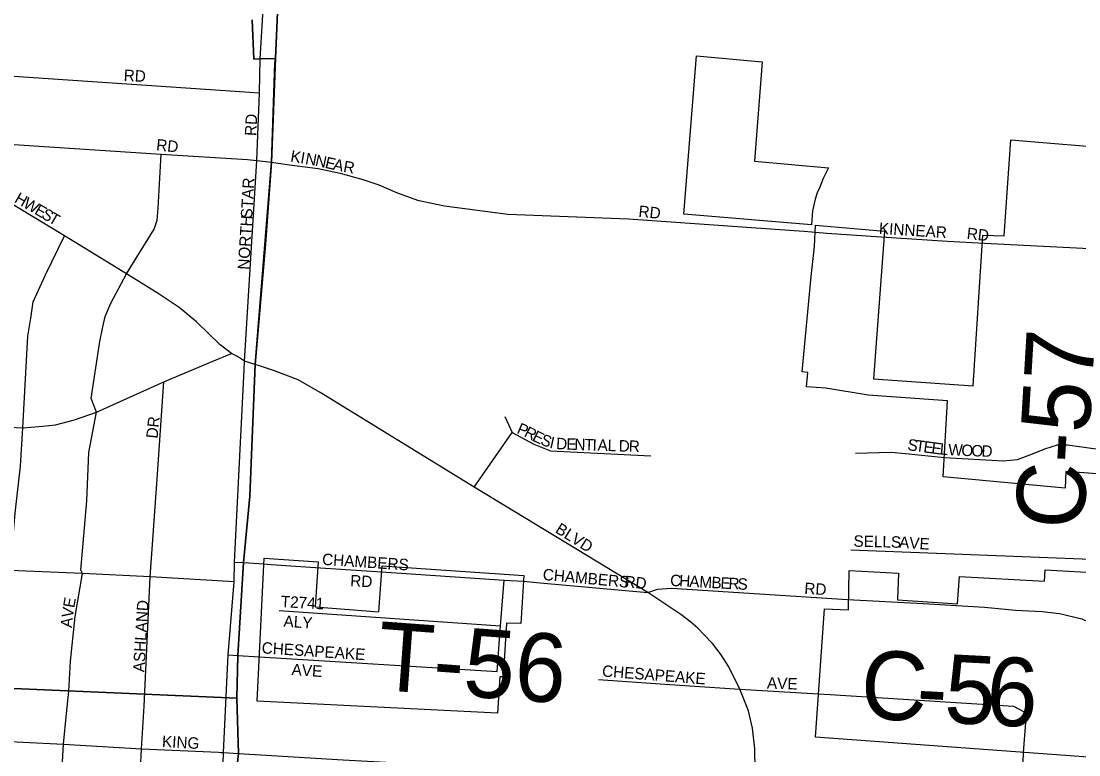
# Model space of a CAD drawing. Extents: x 0 to 34, y -6.2 to 22.
# Drawn here: x 3.949 to 4.825, y 20.105 to 20.712 of the extents above; entities that cross this region are included whole.
import ezdxf

# ---------------------------------------------------------------- set-up
doc = ezdxf.new("R2010")
doc.units = 0
for name, color, linetype in [('GM_X_City_Street', 7, 'Continuous'), ('GM_X_City_Street_Text', 7, 'Continuous'), ('GM_X_Corporation', 7, 'Continuous'), ('GM_X_County_Road', 7, 'Continuous'), ('GM_X_County_Road_Text', 7, 'Continuous'), ('GM_X_Township', 7, 'Continuous'), ('GM_X_Township_Road', 7, 'Continuous'), ('GM_X_Township_Road_Text', 7, 'Continuous'), ('GM_X_Township_Subdivision', 7, 'Continuous'), ('GM_X_Township_Subdivision_Text', 7, 'Continuous')]:
    doc.layers.add(name, color=color, linetype=linetype)

msp = doc.modelspace()

# ---------------------------------------------------------------- linework, layer by layer
at = {"layer": 'GM_X_City_Street'}
for points in [[(4.13376, 20.42379), (4.13412, 20.431), (4.14426, 20.59719), (4.1464, 20.65308), (4.147, 20.68115), (4.14903, 20.7131), (4.15248, 20.77439), (4.15528, 20.83689), (4.15851, 20.89864), (4.16128, 20.96059), (4.16518, 21.02174), (4.16674, 21.05187)], [(4.14634, 20.42702), (4.14285, 20.42815), (4.13412, 20.431), (4.1282, 20.43462), (4.12327, 20.43725), (4.11389, 20.44448), (4.09417, 20.46339), (4.07987, 20.47522), (4.06256, 20.48701), (4.03647, 20.50333), (3.985, 20.53457), (3.93355, 20.56597), (3.90938, 20.58159), (3.89656, 20.5913), (3.88504, 20.60083), (3.87921, 20.60699), (3.87288, 20.61497), (3.8654, 20.62434), (3.85841, 20.6342), (3.85316, 20.64308), (3.83619, 20.67417), (3.80432, 20.73465)], [(3.70199, 20.67304), (3.71088, 20.67647), (3.72097, 20.67936), (3.73018, 20.68108), (3.74055, 20.68137), (3.83619, 20.67417), (3.92237, 20.66823), (4.13851, 20.65374), (4.1464, 20.65308)], [(3.87288, 20.61497), (3.97235, 20.60839), (4.06493, 20.60226), (4.13637, 20.59801), (4.14426, 20.59719)], [(3.98852, 20.15761), (3.98993, 20.18253), (3.99386, 20.21942), (3.99982, 20.25504), (3.99854, 20.25784), (4.00348, 20.31526), (4.00512, 20.35519), (4.01138, 20.3887), (4.00711, 20.40006), (4.01427, 20.44711), (4.01674, 20.45927), (4.01871, 20.46782), (4.02331, 20.47884), (4.03647, 20.50333), (4.05914, 20.54008), (4.06173, 20.54757), (4.06259, 20.55765), (4.06493, 20.60226)], [(4.14426, 20.59719), (4.15415, 20.59589)], [(4.15415, 20.59589), (4.15632, 20.59561), (4.17125, 20.59355), (4.19501, 20.59034), (4.21331, 20.58649), (4.23194, 20.58135), (4.24511, 20.57685), (4.25988, 20.57043), (4.27722, 20.56433), (4.29945, 20.55952), (4.35201, 20.55267), (4.45186, 20.54871), (4.58895, 20.53904), (4.59711, 20.5384)], [(3.92243, 20.16057), (3.92756, 20.19545), (3.94002, 20.25755), (3.94431, 20.30502), (3.94857, 20.34398), (3.95057, 20.37564), (3.95459, 20.45152), (3.95711, 20.46659), (3.95912, 20.47996), (3.96922, 20.50245), (3.985, 20.53457)], [(4.65682, 20.53418), (4.7159, 20.53022), (4.74644, 20.52863)], [(3.6467, 20.38724), (3.64986, 20.38706), (3.6529, 20.38689), (3.70425, 20.38446), (3.76666, 20.38519), (3.82847, 20.38167), (3.88977, 20.37866), (3.95057, 20.37564), (3.96716, 20.37715), (3.97771, 20.37815), (3.99329, 20.38217), (4.01138, 20.3887), (4.06732, 20.41371), (4.10579, 20.42999), (4.12327, 20.43725)], [(4.11946, 20.16473), (4.12057, 20.18764), (4.12545, 20.24801), (4.12574, 20.26449), (4.13376, 20.42379)], [(4.55628, 20.08526), (4.55664, 20.09249), (4.55647, 20.10992), (4.55433, 20.12701), (4.55105, 20.14132), (4.54402, 20.15913), (4.53474, 20.17767), (4.52852, 20.18768), (4.52129, 20.19705), (4.51422, 20.20462), (4.50912, 20.20987), (4.50344, 20.21461), (4.49515, 20.22105), (4.4677, 20.2393), (4.324, 20.3266), (4.19675, 20.40486), (4.17844, 20.41553), (4.15875, 20.42298), (4.14634, 20.42702)], [(4.05083, 20.14511), (4.05593, 20.25236), (4.06157, 20.32921), (4.06732, 20.41371)], [(4.34952, 20.38504), (4.35563, 20.37175), (4.37358, 20.36205), (4.38724, 20.35666), (4.47021, 20.35235)], [(4.324, 20.3266), (4.35563, 20.37175)], [(4.63964, 20.35481), (4.66916, 20.35545), (4.68108, 20.35426)], [(4.63583, 20.27455), (4.84847, 20.26641)], [(4.12545, 20.24801), (4.05593, 20.25236), (3.99982, 20.25504), (3.94002, 20.25755), (3.87973, 20.26107), (3.81805, 20.26424), (3.7657, 20.26676)], [(4.12574, 20.26449), (4.13308, 20.26403), (4.14993, 20.26297), (4.15619, 20.26254)], [(4.19678, 20.25978), (4.24751, 20.25633)], [(4.37869, 20.2473), (4.4677, 20.2393)], [(4.4677, 20.2393), (4.47595, 20.24197), (4.48734, 20.24285), (4.63308, 20.23355), (4.69563, 20.23004)], [(4.12057, 20.18764), (4.12848, 20.18711), (4.14629, 20.18593)], [(4.11655, 20.10492), (4.11664, 20.10677), (4.11946, 20.16473)], [(4.42713, 20.16714), (4.48178, 20.1634), (4.54402, 20.15913), (4.58576, 20.15684), (4.60916, 20.15542), (4.61869, 20.15481)], [(3.96346, 19.67023), (3.98059, 19.91279), (3.98086, 19.92294), (3.98244, 20.08445), (3.98408, 20.11355), (3.98655, 20.13903), (3.98852, 20.15761)], [(4.03954, 19.92149), (4.04886, 20.10993), (4.05083, 20.14511)], [(3.74433, 20.12703), (3.78515, 20.12473), (3.85108, 20.12062), (3.91718, 20.117), (3.98408, 20.11355), (4.04886, 20.10993), (4.11253, 20.10694), (4.11465, 20.10685)], [(4.10661, 19.91804), (4.11352, 20.04512), (4.11655, 20.10492)], [(4.11465, 20.10685), (4.11664, 20.10677), (4.12905, 20.10601), (4.21566, 20.1007), (4.28652, 20.09692), (4.3651, 20.09199), (4.49614, 20.08542), (4.52499, 20.08415)], [(4.73722, 19.58334), (4.73968, 19.62181), (4.7422, 19.63051), (4.74531, 19.64456), (4.74615, 19.65938), (4.75199, 19.74324), (4.76318, 19.87149), (4.76179, 19.88392), (4.76731, 19.96792), (4.77381, 20.01883), (4.77743, 20.06963), (4.77874, 20.10662)]]:
    msp.add_lwpolyline(points, dxfattribs=at)
at = {"layer": 'GM_X_Corporation'}
for points in [[(4.17585, 21.05642), (4.15959, 20.68147), (4.15923, 20.67757), (4.15632, 20.59561), (4.15136, 20.5277), (4.14285, 20.42815), (4.13842, 20.31918), (4.13308, 20.26403), (4.12848, 20.18711), (4.1276, 20.15181), (3.77081, 20.16721)], [(3.77081, 20.16721), (4.1276, 20.15181), (4.12848, 20.18711), (4.13308, 20.26403), (4.13842, 20.31918), (4.14285, 20.42815), (4.15136, 20.5277), (4.15632, 20.59561), (4.15923, 20.67757), (4.15959, 20.68147), (4.17585, 21.05642)], [(4.50817, 20.68366), (4.56237, 20.67892), (4.55605, 20.5966), (4.61737, 20.59086), (4.61293, 20.58211), (4.61007, 20.57491), (4.60803, 20.57038), (4.60629, 20.56505), (4.60424, 20.55533), (4.60322, 20.54379), (4.49764, 20.55264), (4.50817, 20.68366)], [(4.6003, 20.42141), (4.59566, 20.42204), (4.60299, 20.50101), (4.60568, 20.52571), (4.60667, 20.54345), (4.66374, 20.53852), (4.65467, 20.41614), (4.73714, 20.41033), (4.74502, 20.53517), (4.76268, 20.53459), (4.76836, 20.61427), (4.86116, 20.6064)], [(4.85086, 20.33659), (4.81381, 20.33952), (4.81331, 20.32574), (4.71238, 20.335), (4.71595, 20.3979), (4.65021, 20.40271), (4.6151, 20.40864), (4.59908, 20.40952), (4.6003, 20.42141)], [(4.15015, 20.26762), (4.1949, 20.26466), (4.19245, 20.2274), (4.24532, 20.22333), (4.24782, 20.26131), (4.36515, 20.2534), (4.3628, 20.21368), (4.35078, 20.21396), (4.34814, 20.16954), (4.3453, 20.16954), (4.34351, 20.13947), (4.14457, 20.1493), (4.15015, 20.26762)], [(4.84351, 20.10198), (4.60673, 20.11958), (4.61391, 20.22562), (4.63396, 20.22482), (4.63452, 20.25758), (4.6752, 20.25534), (4.67446, 20.23323), (4.72423, 20.2299), (4.72565, 20.25256), (4.79626, 20.24867), (4.79674, 20.25812), (4.84545, 20.25539)]]:
    msp.add_lwpolyline(points, dxfattribs=at)
at = {"layer": 'GM_X_County_Road'}
for points in [[(4.59711, 20.5384), (4.61611, 20.5369), (4.65682, 20.53418)], [(4.74644, 20.52863), (4.866, 20.5224)], [(4.69563, 20.23004), (4.74659, 20.22718), (4.77205, 20.22466), (4.79408, 20.22342), (4.80853, 20.22177), (4.82698, 20.21737), (4.83864, 20.21202), (4.84859, 20.20746), (4.92044, 20.17814), (4.98886, 20.15061), (5.00531, 20.14388), (5.0237, 20.13638), (5.03604, 20.13276), (5.05182, 20.13095), (5.08454, 20.12865), (5.1667, 20.12366), (5.19778, 20.1218)]]:
    msp.add_lwpolyline(points, dxfattribs=at)
at = {"layer": 'GM_X_Township'}
for points in [[(3.91113, 19.92982), (3.98086, 19.92295), (4.03954, 19.92149), (4.04759, 19.92099), (4.10661, 19.91804), (4.11492, 19.91758), (4.12225, 20.04451), (4.12905, 20.10601), (4.1276, 20.15181), (4.12848, 20.18711), (4.13308, 20.26403), (4.13842, 20.31918), (4.14285, 20.42815), (4.15632, 20.59561), (4.15959, 20.68147), (4.14699, 20.68115), (4.14165, 20.68104), (4.14048, 20.71359)], [(4.14048, 20.71359), (4.14165, 20.68104), (4.14699, 20.68115), (4.15959, 20.68147), (4.15632, 20.59561), (4.14285, 20.42815), (4.13842, 20.31918), (4.13308, 20.26403), (4.12848, 20.18711), (4.1276, 20.15181), (4.12905, 20.10601), (4.12225, 20.04451), (4.11492, 19.91758), (4.12106, 19.91725), (4.19453, 19.91272), (4.27333, 19.90633), (4.35119, 19.90135), (4.54291, 19.88718), (4.64043, 19.87993), (4.70068, 19.87656), (4.76318, 19.87149), (4.81836, 19.86698), (4.82511, 19.86698)]]:
    msp.add_lwpolyline(points, dxfattribs=at)
at = {"layer": 'GM_X_Township_Road'}
for points in [[(4.15619, 20.26254), (4.19678, 20.25978)], [(4.24751, 20.25633), (4.34898, 20.24943), (4.36487, 20.24854), (4.37869, 20.2473)]]:
    msp.add_lwpolyline(points, dxfattribs=at)
at = {"layer": 'GM_X_Township_Subdivision'}
for points in [[(4.68108, 20.35426), (4.71329, 20.35104), (4.7622, 20.34844), (4.77386, 20.34956), (4.78629, 20.35409), (4.79644, 20.35823), (4.80699, 20.36162), (4.81527, 20.36162), (4.83672, 20.35861), (4.85479, 20.35747)], [(4.343, 20.17381), (4.34583, 20.21163), (4.34898, 20.24943)], [(4.16259, 20.22439), (4.34583, 20.21163)], [(4.14629, 20.18593), (4.343, 20.17381)], [(4.61869, 20.15481), (4.77038, 20.14511), (4.77931, 20.14031), (4.78072, 20.13161)], [(4.77874, 20.10662), (4.78072, 20.13161)]]:
    msp.add_lwpolyline(points, dxfattribs=at)

# ---------------------------------------------------------------- texts
at = {"layer": 'GM_X_City_Street_Text'}
for s, rotation, p in [('RD', 356.98842, (4.03384, 20.66305)), ('RD', 86.98901, (4.14364, 20.61721)), ('RD', 353.99459, (4.0606, 20.60555)), ('K', 350.18194, (4.17154, 20.59633)), ('I', 350.15667, (4.17975, 20.59491)), ('N', 350.19392, (4.18386, 20.5942)), ('N', 348.27004, (4.19199, 20.5928)), ('E', 346.73914, (4.20008, 20.59112)), ('A', 347.74136, (4.20675, 20.58955)), ('R', 350.17804, (4.21532, 20.58769)), ('STAR', 86.81579, (4.1403, 20.54888)), ('H', 329.67847, (3.94289, 20.56299)), ('W', 329.68035, (3.95009, 20.55878)), ('E', 329.66883, (3.95944, 20.55332)), ('S', 329.70691, (3.9652, 20.54994)), ('T', 329.66883, (3.97095, 20.54658)), ('RD', 353.99459, (4.45976, 20.55051)), ('NORTH', 86.42564, (4.1378, 20.50639)), ('KINNEAR', 356.30692, (4.65886, 20.53636)), ('RD', 353.66381, (4.73144, 20.53218)), ('DR', 83.99458, (4.06198, 20.36646)), ('P', 336.77271, (4.35871, 20.37148)), ('R', 332.97885, (4.36468, 20.36892)), ('E', 333.70671, (4.37148, 20.36545)), ('S', 338.28337, (4.37821, 20.36216)), ('I', 347.50112, (4.38599, 20.35921)), ('D', 356.85152, (4.39173, 20.35808)), ('E', 358.04657, (4.40027, 20.35761)), ('N', 358.0675, (4.40694, 20.35738)), ('T', 358.0599, (4.41526, 20.3571)), ('I', 358.0326, (4.42193, 20.35687)), ('A', 358.0326, (4.42609, 20.35673)), ('L', 358.07144, (4.43443, 20.35644)), ('D', 358.0562, (4.44359, 20.35613)), ('R', 358.0326, (4.45192, 20.35585)), ('BLVD', 327.99523, (4.39052, 20.28945)), ('SELLS', 358.6036, (4.63795, 20.27723)), ('AVE', 356.0499, (4.67553, 20.27639)), ('CHAMBERS', 356.23517, (4.19803, 20.26222)), ('CHAMBERS', 354.73764, (4.38057, 20.24972)), ('RD', 356.98902, (4.22133, 20.24447)), ('RD', 353.99459, (4.4481, 20.24388)), ('C', 357.30372, (4.48613, 20.24473)), ('H', 356.96079, (4.4936, 20.24438)), ('A', 356.96079, (4.50193, 20.24394)), ('M', 356.93839, (4.51025, 20.24349)), ('B', 356.96227, (4.52024, 20.24296)), ('E', 356.93839, (4.52773, 20.24256)), ('R', 356.96227, (4.53439, 20.24221)), ('S', 356.93839, (4.54188, 20.24181)), ('RD', 356.98902, (4.59717, 20.23805)), ('E', 80.06164, (3.99308, 20.22608)), ('ASHLAND', 86.53376, (4.05113, 20.17305)), ('V', 81.59785, (3.99188, 20.2179)), ('A', 84.76995, (3.99113, 20.20974)), ('CHESAPEAKE', 355.55264, (4.42972, 20.16972)), ('AVE', 358.0261, (4.5663, 20.15972)), ('KING', 356.73129, (4.06551, 20.11139))]:
    msp.add_text(s, height=0.00947, rotation=rotation, dxfattribs=at).set_placement(p)
at = {"layer": 'GM_X_County_Road_Text'}
for s, height, rotation, p in [('C-57', 0.056818, 86.57343, (4.82837, 20.29066)), ('C', 0.05682, 357.03584, (4.643, 20.13516)), ('5', 0.05682, 357.03529, (4.71236, 20.13157)), ('6', 0.05682, 357.02038, (4.74703, 20.12977)), ('-', 0.05682, 357.03583, (4.68926, 20.13276))]:
    msp.add_text(s, height=height, rotation=rotation, dxfattribs=at).set_placement(p)
at = {"layer": 'GM_X_Township_Road_Text'}
msp.add_text('T-56', height=0.056818, rotation=355.81411, dxfattribs=at).set_placement((4.24244, 20.15876))
at = {"layer": 'GM_X_Township_Subdivision_Text'}
for s, rotation, p in [('S', 352.35299, (4.68232, 20.35721)), ('T', 352.3259, (4.68892, 20.35633)), ('E', 352.34673, (4.69553, 20.35544)), ('E', 352.3259, (4.70214, 20.35455)), ('L', 354.65448, (4.70916, 20.35361)), ('W', 357.53872, (4.71632, 20.35295)), ('O', 357.7073, (4.72717, 20.35249)), ('O', 357.71845, (4.7355, 20.35216)), ('D', 357.70415, (4.74383, 20.35183)), ('T2741', 356.82185, (4.16384, 20.22721)), ('ALY', 356.05688, (4.16608, 20.21097)), ('CHESAPEAKE', 356.18802, (4.14803, 20.18889)), ('AVE', 356.05688, (4.17275, 20.17097))]:
    msp.add_text(s, height=0.00947, rotation=rotation, dxfattribs=at).set_placement(p)

doc.saveas('drawing.dxf')
